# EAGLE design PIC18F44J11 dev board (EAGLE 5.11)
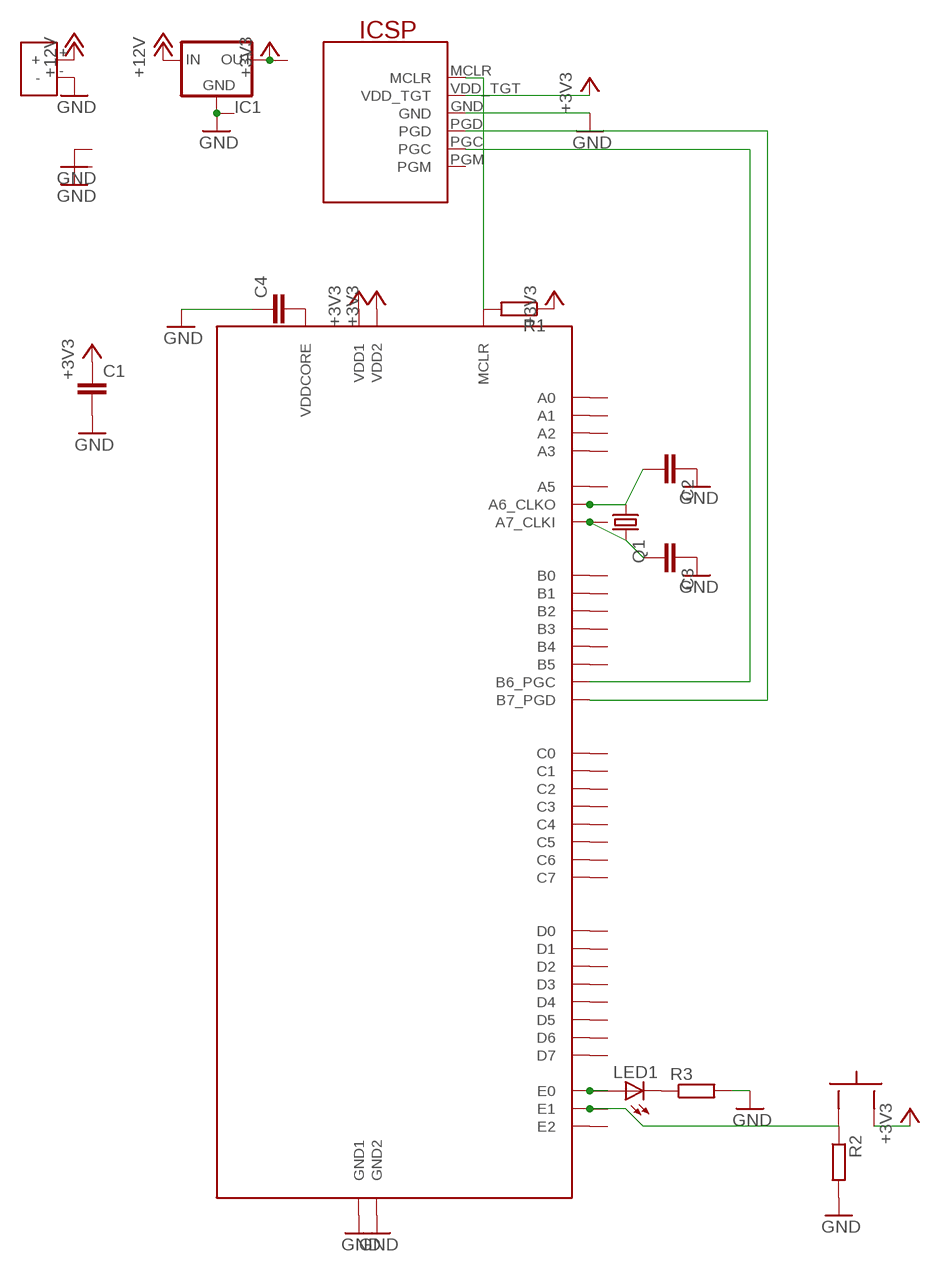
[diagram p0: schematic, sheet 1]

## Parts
C1  C2.5/2  [C2.5-2]
C2  C2.5/2  [C2.5-2]
C3  C2.5/2  [C2.5-2]
C4  C2.5/2  [C2.5-2]
IC1  78LXX  [78LXX]
LED1  LED3MM  [LED3MM]
Q1  CRYSTALHC49S  [HC49/S]
R1  R-EU_0204/2V  [0204V]
R2  R-EU_0204/2V  [0204V]
R3  R-EU_0204/2V  [0204V]
U$1  PIC18F44J11TQFP-44  [TQFP-44]
U$2  ICSP_PICKITSTRAIGHT_6  [ICSP_PICKIT]
U$3  POWER_LEADS  [POWER_LEADS]
U$4  BUTTONEVQ11  [BUTTON_EVQ11]
U$5  HEADER_PIN  [HEADER_PIN]
U$6  HEADER_PIN  [HEADER_PIN]
U$7  HEADER_PIN  [HEADER_PIN]
U$8  HEADER_PIN  [HEADER_PIN]
U$9  HEADER_PIN  [HEADER_PIN]
U$10  HEADER_PIN  [HEADER_PIN]
U$11  HEADER_PIN  [HEADER_PIN]
U$12  HEADER_PIN  [HEADER_PIN]
U$13  HEADER_PIN  [HEADER_PIN]
U$14  HEADER_PIN  [HEADER_PIN]
U$15  HEADER_PIN  [HEADER_PIN]
U$16  HEADER_PIN  [HEADER_PIN]
U$17  HEADER_PIN  [HEADER_PIN]
U$18  HEADER_PIN  [HEADER_PIN]
U$19  HEADER_PIN  [HEADER_PIN]
U$20  HEADER_PIN  [HEADER_PIN]
U$21  HEADER_PIN  [HEADER_PIN]
U$22  HEADER_PIN  [HEADER_PIN]
U$23  HEADER_PIN  [HEADER_PIN]
U$24  HEADER_PIN  [HEADER_PIN]
U$25  HEADER_PIN  [HEADER_PIN]
U$26  HEADER_PIN  [HEADER_PIN]
U$27  HEADER_PIN  [HEADER_PIN]
U$28  HEADER_PIN  [HEADER_PIN]
U$29  HEADER_PIN  [HEADER_PIN]
U$30  HEADER_PIN  [HEADER_PIN]
U$31  HEADER_PIN  [HEADER_PIN]
U$32  HEADER_PIN  [HEADER_PIN]
U$33  HEADER_PIN  [HEADER_PIN]
U$34  HEADER_PIN  [HEADER_PIN]
U$35  HEADER_PIN  [HEADER_PIN]
U$36  HEADER_PIN  [HEADER_PIN]
U$37  HEADER_PIN  [HEADER_PIN]
U$38  HEADER_PIN  [HEADER_PIN]
U$39  HEADER_PIN  [HEADER_PIN]
U$40  HEADER_PIN  [HEADER_PIN]

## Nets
+3V3: C1.1 IC1.OUT R1.1 U$1.7(VDD1) U$1.28(VDD2) U$2.VDD_TGT U$4.P$1 U$39.P$1
+12V: IC1.IN U$3.+
GND: C1.2 C2.1 C3.1 C4.1 IC1.GND R2.2 R3.2 U$1.6(GND1) U$1.29(GND2) U$2.GND U$3.- U$37.P$1 U$38.P$1 U$40.P$1
N$1: C2.2 Q1.1 U$1.31(A6_CLKO) U$10.P$1
N$2: C3.2 Q1.2 U$1.30(A7_CLKI) U$11.P$1
N$3: LED1.A U$1.25(E0) U$34.P$1
N$4: C4.2 U$1.23(VDDCORE)
N$5: R1.2 U$1.18(MCLR) U$2.MCLR
N$6: U$1.16(B6_PGC) U$2.PGC
N$7: U$1.17(B7_PGD) U$2.PGD
N$8: R2.1 U$1.26(E1) U$4.P$2 U$35.P$1
N$9: LED1.K(C) R3.1
N$10: U$1.19(A0) U$5.P$1
N$11: U$1.20(A1) U$6.P$1
N$12: U$1.21(A2) U$7.P$1
N$13: U$1.22(A3) U$8.P$1
N$14: U$1.24(A5) U$9.P$1
N$15: U$1.8(B0) U$12.P$1
N$16: U$1.9(B1) U$13.P$1
N$17: U$1.10(B2) U$14.P$1
N$18: U$1.11(B3) U$15.P$1
N$19: U$1.14(B4) U$16.P$1
N$20: U$1.15(B5) U$17.P$1
N$21: U$1.32(C0) U$18.P$1
N$22: U$1.35(C1) U$19.P$1
N$23: U$1.36(C2) U$20.P$1
N$24: U$1.37(C3) U$21.P$1
N$25: U$1.42(C4) U$22.P$1
N$26: U$1.43(C5) U$23.P$1
N$27: U$1.44(C6) U$24.P$1
N$28: U$1.1(C7) U$25.P$1
N$29: U$1.38(D0) U$26.P$1
N$30: U$1.39(D1) U$27.P$1
N$31: U$1.40(D2) U$28.P$1
N$32: U$1.41(D3) U$29.P$1
N$33: U$1.2(D4) U$30.P$1
N$34: U$1.3(D5) U$31.P$1
N$35: U$1.4(D6) U$32.P$1
N$36: U$1.5(D7) U$33.P$1
N$37: U$1.27(E2) U$36.P$1
Unconnected: U$2.PGM

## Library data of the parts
C1-C4 = capacitor-wima:C: CAPACITOR
IC1 = v-reg:78LXX: VOLTAGE REGULATOR
LED1 = led:LED: LED
Q1 = crystal:CRYSTAL: CRYSTAL; OC_FARNELL: 1667008; OC_NEWARK: unknown
R1-R3 = resistor:R-EU_: RESISTOR, European symbol
U$1 = hackaday:PIC18F44J11
U$2 = hackaday:ICSP_PICKIT
U$3 = hackaday:POWER_LEADS
U$4 = hackaday:BUTTON
U$5-U$40 = hackaday:HEADER_PIN

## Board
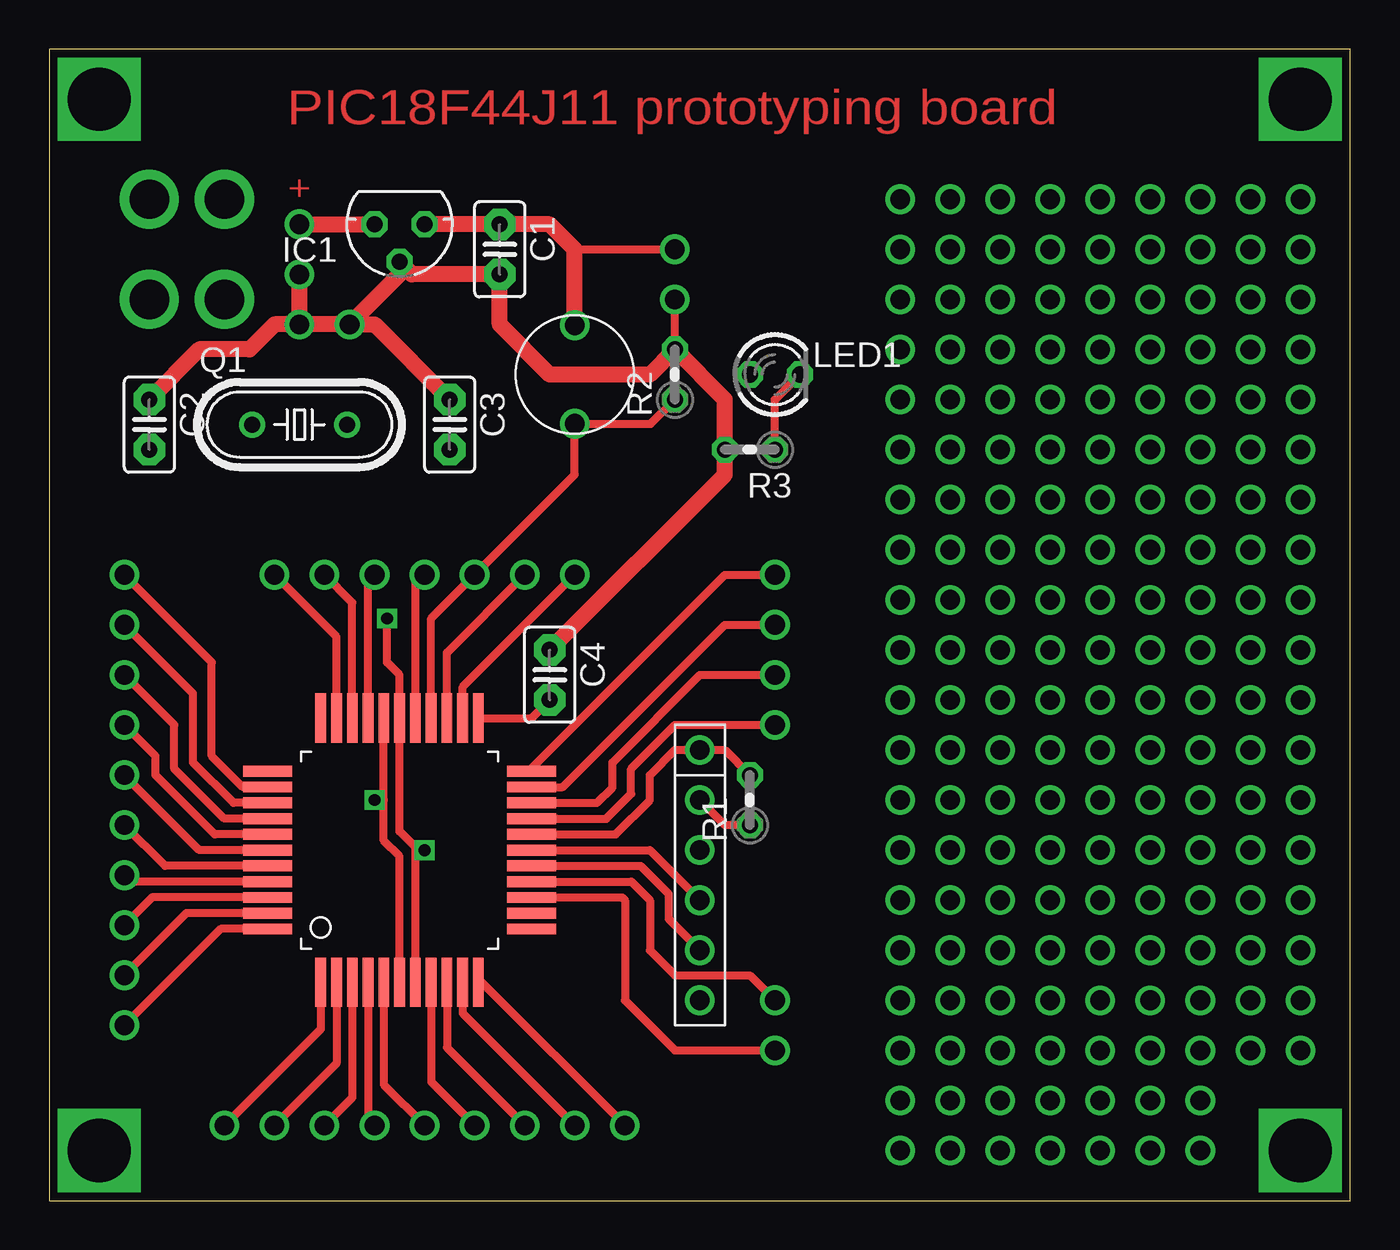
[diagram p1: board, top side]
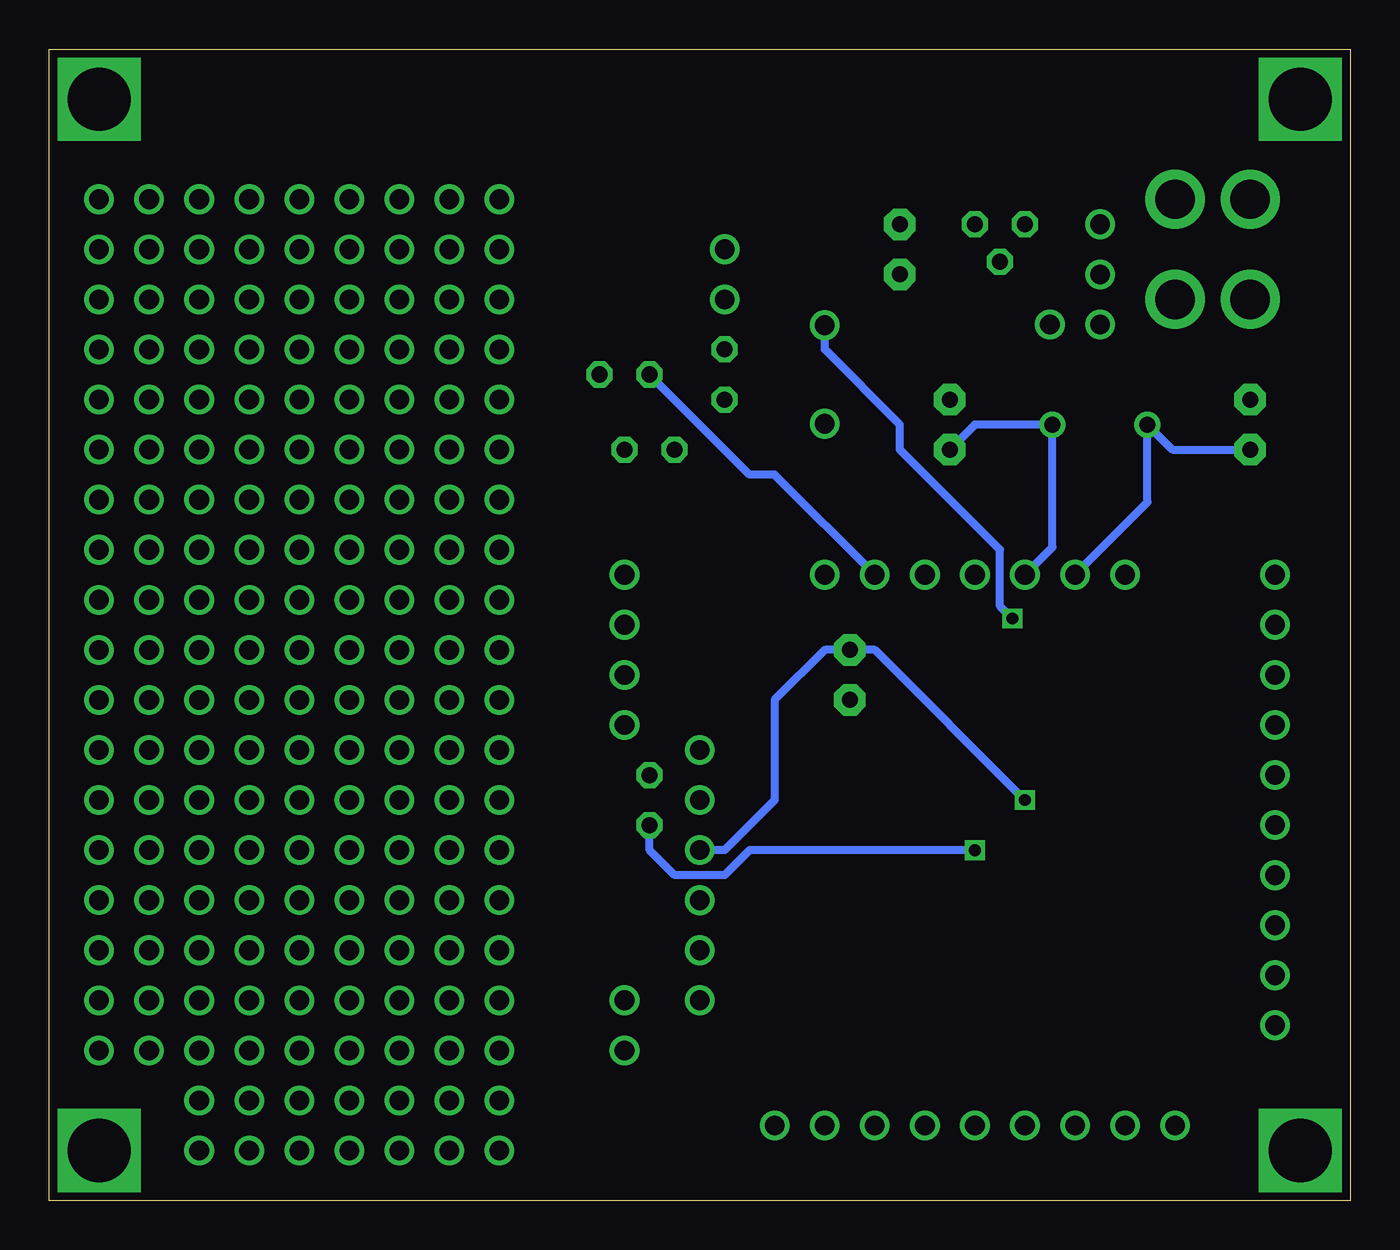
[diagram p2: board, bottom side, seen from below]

Size 66.03 x 58.41 mm. Coordinates in mm from the lower left corner, seen from the top.
Outline: 0,0 66.03,0 66.03,58.41 0,58.41 0,0
Copper layers (1*16): Top 0.035mm / dielectric 1.5mm / Bottom 0.035mm
Design rules "default": minimum track width 10mil, minimum drill 24mil, track to track 8mil, track to pad 8mil, pad to pad 8mil, via to via 8mil, smd to smd 8mil, copper to edge 40mil, drill to drill 8mil, minimum pad ring 10mil, minimum via ring 8mil, stop-mask expansion 4mil, vias tented up to drill 0mil, thermal gap 10mil

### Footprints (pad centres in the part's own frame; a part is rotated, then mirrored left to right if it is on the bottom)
C2.5-2 = drill 0.813 pad 1.6 octagon: 1 -1.27,0; 2 1.27,0
78LXX = drill 0.813 octagon: GND 0,1.905; IN 1.27,0; OUT -1.27,0
LED3MM = drill 0.813 octagon: A -1.27,0; K 1.27,0
HC49/S = drill 0.813 round: 1 -2.413,0; 2 2.413,0
0204V = drill 0.813 octagon: 1 -1.27,0; 2 1.27,0
TQFP-44 = smd 0.55 x 2.5: 1 -4,-6.7; 2 -3.2,-6.7; 3 -2.4,-6.7; 4 -1.6,-6.7; 5 -0.8,-6.7; 6 0,-6.7; 7 0.8,-6.7; 8 1.6,-6.7; 9 2.4,-6.7; 10 3.2,-6.7; 11 4,-6.7; 23 4,6.7; 24 3.2,6.7; 25 2.4,6.7; 26 1.6,6.7; 27 0.8,6.7; 28 0,6.7; 29 -0.8,6.7; 30 -1.6,6.7; 31 -2.4,6.7; 32 -3.2,6.7; 33 -4,6.7 | smd 2.5 x 0.55: 12 6.7,-4; 13 6.7,-3.2; 14 6.7,-2.4; 15 6.7,-1.6; 16 6.7,-0.8; 17 6.7,0; 18 6.7,0.8; 19 6.7,1.6; 20 6.7,2.4; 21 6.7,3.2; 22 6.7,4; 34 -6.7,4; 35 -6.7,3.2; 36 -6.7,2.4; 37 -6.7,1.6; 38 -6.7,0.8; 39 -6.7,0; 40 -6.7,-0.8; 41 -6.7,-1.6; 42 -6.7,-2.4; 43 -6.7,-3.2; 44 -6.7,-4
ICSP_PICKIT = drill 1 round: GND 0,1.27; MCLR 0,6.35; PGC 0,-3.81; PGD 0,-1.27; PGM 0,-6.35; VDD_TGT 0,3.81
POWER_LEADS = drill 1 round: + 0,1.27; - 0,-1.27 | drill 2 round: P$3 -3.81,2.54; P$4 -3.81,-2.54; P$5 -7.62,-2.54; P$6 -7.62,2.54
BUTTON_EVQ11 = drill 1 round: P$1 0,2.5; P$2 0,-2.5
HEADER_PIN = drill 1 round: P$1 0,0

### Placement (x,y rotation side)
C1  22.86,48.26 270 top
C2  5.08,39.37 270 top
C3  20.32,39.37 270 top
C4  25.4,26.67 270 top
IC1  17.78,49.53 180 top
LED1  36.83,41.91 0 top
Q1  12.7,39.37 0 top
R1  35.56,20.32 90 top
R2  31.75,41.91 90 top
R3  35.56,38.1 180 top
U$1  17.78,17.78 0 top
U$2  33.02,16.51 0 top
U$3  12.7,48.26 0 top
U$4  26.67,41.91 0 top
U$5  36.83,24.13 0 top
U$6  36.83,26.67 0 top
U$7  36.83,29.21 0 top
U$8  36.83,31.75 0 top
U$9  26.67,31.75 0 top
U$10  13.97,31.75 0 top
U$11  16.51,31.75 0 top
U$12  21.59,3.81 0 top
U$13  24.13,3.81 0 top
U$14  26.67,3.81 0 top
U$15  29.21,3.81 0 top
U$16  36.83,7.62 0 top
U$17  36.83,10.16 0 top
U$18  11.43,31.75 0 top
U$19  3.81,31.75 0 top
U$20  3.81,29.21 0 top
U$21  3.81,26.67 0 top
U$22  3.81,13.97 0 top
U$23  3.81,11.43 0 top
U$24  3.81,8.89 0 top
U$25  8.89,3.81 0 top
U$26  3.81,24.13 0 top
U$27  3.81,21.59 0 top
U$28  3.81,19.05 0 top
U$29  3.81,16.51 0 top
U$30  11.43,3.81 0 top
U$31  13.97,3.81 0 top
U$32  16.51,3.81 0 top
U$33  19.05,3.81 0 top
U$34  24.13,31.75 0 top
U$35  21.59,31.75 0 top
U$36  19.05,31.75 0 top
U$37  12.7,44.45 0 top
U$38  15.24,44.45 0 top
U$39  31.75,48.26 0 top
U$40  31.75,45.72 0 top

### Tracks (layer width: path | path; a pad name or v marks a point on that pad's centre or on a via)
+3V3  (via drill 0.6)
  Top 0.406: R1.1 34.29,19.05 U$2.VDD_TGT | 18.58,17.93 17.78,18.73 U$1.28 17.78,26.67 17.14,27.3 v17.14,29.53 | 18.58,17.93 18.9,17.93 v19.05,17.78 | 26.67,48.26 U$39.P$1 | U$1.7 18.58,17.93
  Top 0.813: IC1.OUT C1.1 25.4,49.53 26.67,48.26 U$4.P$1
  Bottom 0.406: U$4.P$1 26.67,43.18 22.86,39.37 22.86,38.1 17.78,33.02 17.78,30.16 v17.14,29.53 | v19.05,17.78 30.48,17.78 31.75,16.51 34.29,16.51 35.56,17.78 R1.1
+12V
  Top 0.813: U$3.+ IC1.IN
GND  (via drill 0.6)
  Top 0.406: 16.98,20.32 16.98,18.26 17.78,17.46 U$1.6 | 16.98,20.32 U$1.29 | 16.98,20.32 v16.51,20.32 | R2.2 U$40.P$1
  Top 0.813: U$38.P$1 17.78,46.99 IC1.GND 18.41,46.99 C1.2 22.86,44.45 25.4,41.91 30.48,41.91 R2.2 34.29,40.64 R3.2 34.29,36.83 C4.1 | U$38.P$1 U$37.P$1 | U$37.P$1 U$3.- | U$37.P$1 11.43,44.45 10.16,43.18 7.62,43.18 C2.1 | U$38.P$1 16.51,44.45 C3.1
  Bottom 0.406: U$2.GND 31.75,17.78 29.21,20.32 29.21,25.4 26.67,27.94 C4.1 24.13,27.94 v16.51,20.32
N$1
  Top 0.406: U$1.31 15.38,30.34 U$10.P$1
  Bottom 0.406: C2.2 9.02,38.1 Q1.1 10.29,35.43 U$10.P$1
N$2
  Top 0.406: U$1.30 16.18,31.42 U$11.P$1
  Bottom 0.406: U$11.P$1 15.11,33.15 Q1.2 19.05,39.37 C3.2
N$3
  Top 0.406: U$1.25 20.18,27.8 U$34.P$1
  Bottom 0.406: LED1.A 30.48,36.83 29.21,36.83 U$34.P$1
N$4
  Top 0.406: U$1.23 24.48,24.48 C4.2
N$5
  Top 0.406: U$1.18 28.74,18.58 30.48,20.32 30.48,21.59 31.75,22.86 U$2.MCLR 34.29,22.86 R1.2
N$6
  Top 0.406: U$1.16 30.01,16.98 31.43,15.56 31.43,14.29 U$2.PGC
N$7
  Top 0.406: U$1.17 30.48,17.78 U$2.PGD
N$8
  Top 0.406: U$1.26 19.38,29.54 U$35.P$1 26.67,36.83 U$4.P$2 30.52,39.41 R2.1
N$9
  Top 0.406: R3.1 36.83,40.64 LED1.K
N$10
  Top 0.406: U$1.19 25.73,19.38 28.26,19.37 29.53,20.64 29.53,21.91 31.75,24.13 U$5.P$1
N$11
  Top 0.406: U$1.20 27.8,20.18 28.57,20.95 28.57,22.23 33.02,26.67 U$6.P$1
N$12
  Top 0.406: U$1.21 26.06,20.98 34.29,29.21 U$7.P$1
N$13
  Top 0.406: U$1.22 24.48,21.94 34.29,31.75 U$8.P$1
N$14
  Top 0.406: U$1.24 20.98,26.06 U$9.P$1
N$15
  Top 0.406: U$1.8 19.38,6.02 U$12.P$1
N$16
  Top 0.406: U$1.9 20.18,7.76 U$13.P$1
N$17
  Top 0.406: U$1.10 20.98,9.5 U$14.P$1
N$18
  Top 0.406: U$1.11 21.94,11.08 U$15.P$1
N$19
  Top 0.406: U$1.14 29.07,15.38 29.21,15.24 29.21,10.16 31.75,7.62 U$16.P$1
N$20
  Top 0.406: U$1.15 29.54,16.18 30.48,15.24 30.48,12.7 31.75,11.43 35.56,11.43 U$17.P$1
N$21
  Top 0.406: U$1.32 14.58,28.6 U$18.P$1
N$22
  Top 0.406: U$1.35 9.82,20.98 8.26,22.54 8.26,27.3 U$19.P$1
N$23
  Top 0.406: U$1.36 9.35,20.18 7.3,22.23 7.3,25.72 U$20.P$1
N$24
  Top 0.406: U$1.37 8.88,19.38 6.35,21.91 6.35,24.13 U$21.P$1
N$25
  Top 0.406: U$1.42 5.22,15.38 U$22.P$1
N$26
  Top 0.406: U$1.43 6.96,14.58 U$23.P$1
N$27
  Top 0.406: U$1.44 8.7,13.78 U$24.P$1
N$28
  Top 0.406: U$1.1 13.78,8.7 U$25.P$1
N$29
  Top 0.406: U$1.38 8.41,18.58 5.4,21.59 5.4,22.54 U$26.P$1
N$30
  Top 0.406: U$1.39 7.62,17.78 U$27.P$1
N$31
  Top 0.406: U$1.40 5.88,16.98 U$28.P$1
N$32
  Top 0.406: U$1.41 4.14,16.18 U$29.P$1
N$33
  Top 0.406: U$1.2 14.58,6.96 U$30.P$1
N$34
  Top 0.406: U$1.3 15.38,5.22 U$31.P$1
N$35
  Top 0.406: U$1.4 16.18,4.14 U$32.P$1
N$36
  Top 0.406: U$1.5 16.98,5.88 U$33.P$1
N$37
  Top 0.406: U$1.27 18.58,31.28 U$36.P$1
N$38  (via drill 1)
  other vias: 43.18,2.54
N$39  (via drill 1)
  other vias: 43.18,5.08
N$40  (via drill 1)
  other vias: 43.18,7.62
N$41  (via drill 1)
  other vias: 43.18,10.16
N$42  (via drill 1)
  other vias: 43.18,12.7
N$43  (via drill 1)
  other vias: 43.18,15.24
N$44  (via drill 1)
  other vias: 43.18,17.78 43.18,17.78
N$45  (via drill 1)
  other vias: 43.18,20.32
N$46  (via drill 1)
  other vias: 43.18,22.86
N$47  (via drill 1)
  other vias: 43.18,25.4
N$48  (via drill 1)
  other vias: 43.18,27.94
N$49  (via drill 1)
  other vias: 43.18,30.48
N$50  (via drill 1)
  other vias: 43.18,33.02
N$51  (via drill 1)
  other vias: 43.18,35.56
N$52  (via drill 1)
  other vias: 43.18,38.1
N$53  (via drill 1)
  other vias: 43.18,40.64
N$54  (via drill 1)
  other vias: 43.18,43.18
N$55  (via drill 1)
  other vias: 43.18,45.72
N$56  (via drill 1)
  other vias: 43.18,48.26
N$57  (via drill 1)
  other vias: 43.18,50.8
N$58  (via drill 1)
  other vias: 45.72,2.54
N$59  (via drill 1)
  other vias: 45.72,5.08
N$60  (via drill 1)
  other vias: 45.72,7.62
N$61  (via drill 1)
  other vias: 45.72,10.16
N$62  (via drill 1)
  other vias: 45.72,12.7
N$63  (via drill 1)
  other vias: 45.72,15.24
N$64  (via drill 1)
  other vias: 45.72,17.78
N$65  (via drill 1)
  other vias: 45.72,20.32
N$66  (via drill 1)
  other vias: 45.72,22.86
N$67  (via drill 1)
  other vias: 45.72,25.4
N$68  (via drill 1)
  other vias: 45.72,27.94
N$69  (via drill 1)
  other vias: 45.72,30.48
N$70  (via drill 1)
  other vias: 45.72,33.02
N$71  (via drill 1)
  other vias: 45.72,35.56
N$72  (via drill 1)
  other vias: 45.72,38.1
N$73  (via drill 1)
  other vias: 45.72,40.64
N$74  (via drill 1)
  other vias: 45.72,43.18
N$75  (via drill 1)
  other vias: 45.72,45.72
N$76  (via drill 1)
  other vias: 45.72,48.26
N$77  (via drill 1)
  other vias: 45.72,50.8
N$78  (via drill 1)
  other vias: 48.26,2.54
N$79  (via drill 1)
  other vias: 48.26,5.08
N$80  (via drill 1)
  other vias: 48.26,7.62
N$81  (via drill 1)
  other vias: 48.26,10.16
N$82  (via drill 1)
  other vias: 48.26,12.7
N$83  (via drill 1)
  other vias: 48.26,15.24
N$84  (via drill 1)
  other vias: 48.26,17.78
N$85  (via drill 1)
  other vias: 48.26,20.32
N$86  (via drill 1)
  other vias: 48.26,22.86
N$87  (via drill 1)
  other vias: 48.26,25.4
N$88  (via drill 1)
  other vias: 48.26,27.94
N$89  (via drill 1)
  other vias: 48.26,30.48
N$90  (via drill 1)
  other vias: 48.26,33.02
N$91  (via drill 1)
  other vias: 48.26,35.56
N$92  (via drill 1)
  other vias: 48.26,38.1
N$93  (via drill 1)
  other vias: 48.26,40.64
N$94  (via drill 1)
  other vias: 48.26,43.18
N$95  (via drill 1)
  other vias: 48.26,45.72
N$96  (via drill 1)
  other vias: 48.26,48.26
N$97  (via drill 1)
  other vias: 48.26,50.8
N$98  (via drill 1)
  other vias: 50.8,2.54
N$99  (via drill 1)
  other vias: 50.8,5.08
N$100  (via drill 1)
  other vias: 50.8,7.62
N$101  (via drill 1)
  other vias: 50.8,10.16
N$102  (via drill 1)
  other vias: 50.8,12.7
N$103  (via drill 1)
  other vias: 50.8,15.24
N$104  (via drill 1)
  other vias: 50.8,17.78
N$105  (via drill 1)
  other vias: 50.8,20.32
N$106  (via drill 1)
  other vias: 50.8,22.86
N$107  (via drill 1)
  other vias: 50.8,25.4
N$108  (via drill 1)
  other vias: 50.8,27.94
N$109  (via drill 1)
  other vias: 50.8,30.48
N$110  (via drill 1)
  other vias: 50.8,33.02
N$111  (via drill 1)
  other vias: 50.8,35.56
N$112  (via drill 1)
  other vias: 50.8,38.1
N$113  (via drill 1)
  other vias: 50.8,40.64
N$114  (via drill 1)
  other vias: 50.8,43.18
N$115  (via drill 1)
  other vias: 50.8,45.72
N$116  (via drill 1)
  other vias: 50.8,48.26
N$117  (via drill 1)
  other vias: 50.8,50.8
N$118  (via drill 1)
  other vias: 53.34,2.54
N$119  (via drill 1)
  other vias: 53.34,5.08
N$120  (via drill 1)
  other vias: 53.34,7.62
N$121  (via drill 1)
  other vias: 53.34,10.16
N$122  (via drill 1)
  other vias: 53.34,12.7
N$123  (via drill 1)
  other vias: 53.34,15.24
N$124  (via drill 1)
  other vias: 53.34,17.78
N$125  (via drill 1)
  other vias: 53.34,20.32
N$126  (via drill 1)
  other vias: 53.34,22.86
N$127  (via drill 1)
  other vias: 53.34,25.4
N$128  (via drill 1)
  other vias: 53.34,27.94
N$129  (via drill 1)
  other vias: 53.34,30.48
N$130  (via drill 1)
  other vias: 53.34,33.02
N$131  (via drill 1)
  other vias: 53.34,35.56
N$132  (via drill 1)
  other vias: 53.34,38.1
N$133  (via drill 1)
  other vias: 53.34,40.64
N$134  (via drill 1)
  other vias: 53.34,43.18
N$135  (via drill 1)
  other vias: 53.34,45.72
N$136  (via drill 1)
  other vias: 53.34,48.26
N$137  (via drill 1)
  other vias: 53.34,50.8
N$138  (via drill 1)
  other vias: 55.88,2.54
N$139  (via drill 1)
  other vias: 55.88,5.08
N$140  (via drill 1)
  other vias: 55.88,7.62
N$141  (via drill 1)
  other vias: 55.88,10.16
N$142  (via drill 1)
  other vias: 55.88,12.7
N$143  (via drill 1)
  other vias: 55.88,15.24
N$144  (via drill 1)
  other vias: 55.88,17.78
N$145  (via drill 1)
  other vias: 55.88,20.32
N$146  (via drill 1)
  other vias: 55.88,22.86
N$147  (via drill 1)
  other vias: 55.88,25.4
N$148  (via drill 1)
  other vias: 55.88,27.94
N$149  (via drill 1)
  other vias: 55.88,30.48
N$150  (via drill 1)
  other vias: 55.88,33.02
N$151  (via drill 1)
  other vias: 55.88,35.56
N$152  (via drill 1)
  other vias: 55.88,38.1
N$153  (via drill 1)
  other vias: 55.88,40.64
N$154  (via drill 1)
  other vias: 55.88,43.18
N$155  (via drill 1)
  other vias: 55.88,45.72
N$156  (via drill 1)
  other vias: 55.88,48.26
N$157  (via drill 1)
  other vias: 55.88,50.8
N$158  (via drill 1)
  other vias: 58.42,2.54
N$159  (via drill 1)
  other vias: 58.42,5.08
N$160  (via drill 1)
  other vias: 58.42,7.62
N$161  (via drill 1)
  other vias: 58.42,10.16
N$162  (via drill 1)
  other vias: 58.42,12.7
N$163  (via drill 1)
  other vias: 58.42,15.24
N$164  (via drill 1)
  other vias: 58.42,17.78
N$165  (via drill 1)
  other vias: 58.42,20.32
N$166  (via drill 1)
  other vias: 58.42,22.86
N$167  (via drill 1)
  other vias: 58.42,25.4
N$168  (via drill 1)
  other vias: 58.42,27.94
N$169  (via drill 1)
  other vias: 58.42,30.48
N$170  (via drill 1)
  other vias: 58.42,33.02
N$171  (via drill 1)
  other vias: 58.42,35.56
N$172  (via drill 1)
  other vias: 58.42,38.1
N$173  (via drill 1)
  other vias: 58.42,40.64
N$174  (via drill 1)
  other vias: 58.42,43.18
N$175  (via drill 1)
  other vias: 58.42,45.72
N$176  (via drill 1)
  other vias: 58.42,48.26
N$177  (via drill 1)
  other vias: 58.42,50.8
N$180  (via drill 1)
  other vias: 60.96,7.62
N$181  (via drill 1)
  other vias: 60.96,10.16
N$182  (via drill 1)
  other vias: 60.96,12.7
N$183  (via drill 1)
  other vias: 60.96,15.24
N$184  (via drill 1)
  other vias: 60.96,17.78
N$185  (via drill 1)
  other vias: 60.96,20.32
N$186  (via drill 1)
  other vias: 60.96,22.86
N$187  (via drill 1)
  other vias: 60.96,25.4
N$188  (via drill 1)
  other vias: 60.96,27.94
N$189  (via drill 1)
  other vias: 60.96,30.48
N$190  (via drill 1)
  other vias: 60.96,33.02
N$191  (via drill 1)
  other vias: 60.96,35.56
N$192  (via drill 1)
  other vias: 60.96,38.1
N$193  (via drill 1)
  other vias: 60.96,40.64
N$194  (via drill 1)
  other vias: 60.96,43.18
N$195  (via drill 1)
  other vias: 60.96,45.72
N$196  (via drill 1)
  other vias: 60.96,48.26
N$197  (via drill 1)
  other vias: 60.96,50.8
N$200  (via drill 1)
  other vias: 63.5,7.62
N$201  (via drill 1)
  other vias: 63.5,10.16
N$202  (via drill 1)
  other vias: 63.5,12.7
N$203  (via drill 1)
  other vias: 63.5,15.24
N$204  (via drill 1)
  other vias: 63.5,17.78
N$205  (via drill 1)
  other vias: 63.5,20.32
N$206  (via drill 1)
  other vias: 63.5,22.86
N$207  (via drill 1)
  other vias: 63.5,25.4
N$208  (via drill 1)
  other vias: 63.5,27.94
N$209  (via drill 1)
  other vias: 63.5,30.48
N$210  (via drill 1)
  other vias: 63.5,33.02
N$211  (via drill 1)
  other vias: 63.5,35.56
N$212  (via drill 1)
  other vias: 63.5,38.1
N$213  (via drill 1)
  other vias: 63.5,40.64
N$214  (via drill 1)
  other vias: 63.5,43.18
N$215  (via drill 1)
  other vias: 63.5,45.72
N$216  (via drill 1)
  other vias: 63.5,48.26
N$217  (via drill 1)
  other vias: 63.5,50.8
N$218  (via drill 3.2)
  other vias: 2.54,55.88
N$219  (via drill 3.2)
  other vias: 2.54,2.54
N$220  (via drill 3.2)
  other vias: 63.5,2.54
N$221  (via drill 3.2)
  other vias: 63.5,55.88

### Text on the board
Top: PIC18F44J11 prototyping board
